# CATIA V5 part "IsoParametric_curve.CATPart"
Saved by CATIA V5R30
Part number: Part1
Bounding box of the stored display mesh (mm): x -201.73 to 99, y -122.834 to 226.104, z -13.805 to 30.749
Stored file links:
  D:\PROJECTS\CATIA V56R 2020\Resources\Parts File\c17_catia_v6_6r2020_prt\IsoParametric_curve.CATPart
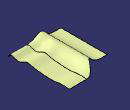
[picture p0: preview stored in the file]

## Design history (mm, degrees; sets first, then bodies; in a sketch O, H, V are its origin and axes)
Body1 (main body)
  Sketch1 on yz-plane, origin (0, 0, 0), H (0, 1, 0), V (0, 0, 1)
    spline S1 through (-122.8344, -6.7669) (-106.6526, 10.0033) (-67.8164, 0) (-14.2694, 18.5355) (14.5636, 14.4165) (64.8742, 7.0611) (133.1319, 3.8248) (184.3252, 10.0033) (226.1036, 7.0611)
    point P1 (-67.8164, 0)
    coincidence: P1 H
  Extrude1: Element1 Sketch1, Lim1 99, Lim2 0
  Sketch2 on zx-plane, origin (0, 0, 0), H (-1, 0, 0), V (0, 0, 1)
    spline S1 through (107.3762, 13.3919) (140.5417, -9.862) (187.902, -13.8052) (201.7301, -13.8052)
  Extrude2: Element1 Sketch2, Lim1 122, Lim2 142
  Blend1: StartLimit {blendlimit Curve edge of Extrude2, Support Extrude2}, EndLimit {blendlimit Curve Sketch1, Support Extrude1}
  Join1: Elements (Extrude2; Blend1; Extrude1)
